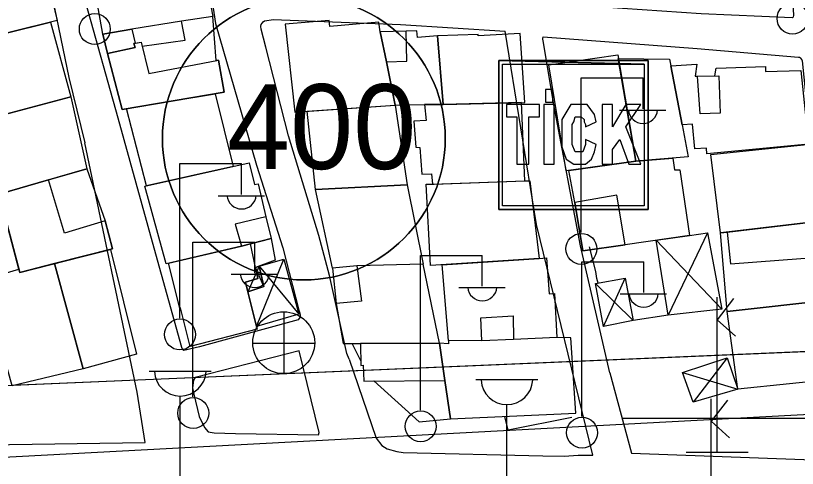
# Model space of a CAD drawing. Extents: x 417997 to 421451, y 4451742 to 4455216.
# Drawn here: x 419193.6 to 419281.9, y 4453640.7 to 4453691.9 of the extents above; entities that cross this region are included whole.
import ezdxf

# ---------------------------------------------------------------- set-up
doc = ezdxf.new("R2010")
doc.units = 0
for name, color, linetype in [('ADAKENARI', 7, 'Continuous'), ('B_Kapi', 7, 'Continuous'), ('B_Mesken', 7, 'Continuous'), ('B_Sundurma', 7, 'Continuous'), ('B_Teras', 7, 'Continuous'), ('KALDIRIM', 7, 'Continuous'), ('LJ_SEMBOL', 7, 'Continuous'), ('PL_TİCK', 7, 'Continuous'), ('S_Cad_Sok_Lambasi', 7, 'Continuous'), ('S_Elektrik_Diregi', 7, 'Continuous'), ('S_Kara_Demy_Trafik_Sinyal', 7, 'Continuous'), ('S_Rogar_Kapagi', 7, 'Continuous'), ('Sinir_Duvar_tek_tarafa_ait', 7, 'Continuous'), ('SM_TAKS', 7, 'Continuous'), ('TR_TİCK', 7, 'Continuous'), ('Yol_Kaldirim_kenari_bordurtasi', 7, 'Continuous'), ('Yol_Sose', 7, 'Continuous')]:
    doc.layers.add(name, color=color, linetype=linetype)

msp = doc.modelspace()

# ---------------------------------------------------------------- linework, layer by layer
at = {"layer": 'ADAKENARI'}
msp.add_line((419123.723, 4453647.173), (419322.839, 4453655.614), dxfattribs=at)
msp.add_line((419123.723, 4453647.173), (419322.839, 4453655.614), dxfattribs=at)
at = {"layer": 'B_Kapi'}
msp.add_lwpolyline([(419259.283, 4453662.174), (419259.171, 4453662.944)], dxfattribs=at)
at = {"layer": 'B_Mesken'}
for points in [[(419203.449, 4453689.791), (419201.814, 4453698.973), (419214.149, 4453700.811), (419215.877, 4453691.806), (419212.331, 4453691.272), (419206.703, 4453690.371)], [(419187.627, 4453688.689), (419185.456, 4453697.539), (419196.149, 4453700.118), (419198.258, 4453691.342)], [(419212.331, 4453691.272), (419206.703, 4453690.371), (419203.449, 4453689.791), (419203.982, 4453687.601), (419205.615, 4453681.291), (419217.156, 4453683.223), (419216.504, 4453686.857), (419216.256, 4453686.81), (419215.877, 4453691.806)], [(419190.17, 4453680.146), (419189.544, 4453679.907), (419187.09, 4453688.417), (419187.627, 4453688.689), (419197.53, 4453691.16), (419199.81, 4453682.704)], [(419224.066, 4453690.944), (419225.127, 4453680.993), (419236.484, 4453681.753), (419235.489, 4453686.652), (419234.799, 4453690.048), (419234.618, 4453691.136), (419229.097, 4453690.661), (419229.021, 4453691.34)], [(419237.712, 4453690.119), (419234.799, 4453690.048), (419235.489, 4453686.652), (419236.484, 4453681.753), (419239.798, 4453681.84), (419241.918, 4453681.825), (419241.274, 4453689.597), (419239.02, 4453689.423), (419238.945, 4453690.156)], [(419241.274, 4453689.597), (419241.918, 4453681.825), (419251.132, 4453682.082), (419250.624, 4453689.853), (419245.867, 4453689.59), (419245.868, 4453689.753)], [(419255.809, 4453674.356), (419253.851, 4453686.344), (419261.638, 4453687.454), (419263.699, 4453675.44)], [(419261.711, 4453687.03), (419267.505, 4453686.983), (419267.644, 4453686.211), (419268.943, 4453679.527), (419269.618, 4453675.937), (419263.699, 4453675.44)], [(419282.327, 4453685.695), (419283.19, 4453677.347), (419271.716, 4453676.268), (419271.673, 4453676.907), (419270.371, 4453676.817), (419270.091, 4453679.637), (419268.943, 4453679.527), (419267.644, 4453686.211), (419270.588, 4453686.414), (419270.407, 4453685.047), (419270.673, 4453685.059), (419272.634, 4453685.076), (419272.784, 4453685.961), (419278.345, 4453686.146), (419278.351, 4453685.57)], [(419191.689, 4453671.712), (419190.521, 4453676.686), (419191.022, 4453676.817), (419190.17, 4453680.146), (419199.81, 4453682.704), (419201.622, 4453674.559)], [(419216.122, 4453683.05), (419218.152, 4453674.841), (419208.381, 4453672.644), (419206.107, 4453681.373)], [(419241.918, 4453681.825), (419239.798, 4453681.84), (419240.001, 4453680.019), (419238.587, 4453679.975), (419238.808, 4453677.013), (419239.27, 4453676.983), (419239.49, 4453673.967), (419240.577, 4453673.986), (419240.686, 4453672.817), (419251.157, 4453673.215), (419250.746, 4453682.071)], [(419227.48, 4453672.227), (419226.525, 4453681.087), (419236.484, 4453681.753), (419237.825, 4453672.751)], [(419273.242, 4453667.327), (419272.169, 4453676.202), (419283.729, 4453677.403), (419284.8, 4453668.679)], [(419267.885, 4453675.791), (419268.064, 4453674.461), (419268.661, 4453674.456), (419269.742, 4453667.042), (419262.491, 4453665.979), (419257.68, 4453665.31), (419256.802, 4453670.769), (419256.098, 4453674.396), (419263.699, 4453675.44)], [(419221.876, 4453669.13), (419222.45, 4453666.69), (419219.106, 4453665.831), (419210.586, 4453663.822), (419208.186, 4453672.601), (419219.988, 4453675.253), (419220.577, 4453672.789), (419220.982, 4453672.877)], [(419201.622, 4453674.559), (419203.706, 4453668.694), (419204.521, 4453665.515), (419197.961, 4453663.846), (419194.058, 4453662.853), (419193.959, 4453663.223), (419191.689, 4453671.712), (419197.308, 4453673.323)], [(419240.472, 4453663.623), (419239.997, 4453672.815), (419240.874, 4453672.817), (419251.157, 4453673.215), (419251.724, 4453673.223), (419252.747, 4453664.433)], [(419239.658, 4453663.804), (419232.154, 4453663.59), (419229.381, 4453663.329), (419227.48, 4453672.227), (419237.825, 4453672.751)], [(419179.471, 4453668.455), (419181.528, 4453659.652), (419190.199, 4453662.11), (419193.959, 4453663.223), (419191.689, 4453671.712), (419190.994, 4453671.434)], [(419274.012, 4453658.445), (419273.242, 4453667.327), (419274.029, 4453667.419), (419284.8, 4453668.679), (419285.31, 4453664.673), (419285.841, 4453659.739)], [(419219.832, 4453660.663), (419220.874, 4453656.423), (419213.316, 4453654.479), (419212.215, 4453658.831), (419212.158, 4453658.817), (419210.862, 4453663.888), (419219.106, 4453665.831), (419220.112, 4453666.089), (419222.45, 4453666.69), (419222.923, 4453664.248), (419220.681, 4453663.406), (419220.948, 4453662.148), (419219.562, 4453661.753), (419219.832, 4453660.663)], [(419204.284, 4453665.454), (419207.256, 4453653.626), (419201.228, 4453651.97), (419197.961, 4453663.846)], [(419252.747, 4453664.433), (419253.589, 4453664.502), (419253.902, 4453660.451), (419254.512, 4453660.478), (419254.756, 4453655.505), (419249.855, 4453655.256), (419246.267, 4453655.132), (419242.529, 4453655.143), (419241.798, 4453663.71)], [(419190.199, 4453662.11), (419193.959, 4453663.223), (419194.058, 4453662.853), (419197.961, 4453663.846), (419201.228, 4453651.97), (419193.177, 4453650.029), (419192.288, 4453653.298), (419192.515, 4453653.359)], [(419229.381, 4453663.329), (419229.809, 4453659.342), (419230.615, 4453654.799), (419232.572, 4453654.811), (419241.489, 4453654.851), (419239.658, 4453663.804), (419232.154, 4453663.59)], [(419274.012, 4453658.445), (419285.841, 4453659.739), (419286.911, 4453650.855), (419275.218, 4453649.668)], [(419242.529, 4453655.143), (419242.498, 4453654.763), (419241.489, 4453654.851), (419242.08, 4453650.635), (419242.756, 4453646.284), (419256.923, 4453646.936), (419256.34, 4453655.471), (419254.756, 4453655.505), (419249.855, 4453655.256), (419246.267, 4453655.132)], [(419242.756, 4453646.284), (419242.08, 4453650.635), (419241.489, 4453654.851), (419232.572, 4453654.811), (419232.607, 4453652.311), (419232.879, 4453652.363), (419232.946, 4453650.569), (419234.089, 4453650.578), (419239.189, 4453645.947)]]:
    msp.add_lwpolyline(points, close=True, dxfattribs=at)
at = {"layer": 'B_Sundurma'}
for p, q in [((419271.79, 4453667.327), (419267.33, 4453658.036)), ((419273.412, 4453658.699), (419265.989, 4453666.492)), ((419220.798, 4453656.731), (419223.893, 4453664.354)), ((419221.106, 4453663.566), (419219.832, 4453660.663)), ((419221.641, 4453661.271), (419220.681, 4453663.406)), ((419221.106, 4453663.566), (419225.59, 4453658.121)), ((419259.143, 4453661.583), (419263.386, 4453657.432)), ((419260.045, 4453656.756), (419262.47, 4453662.187)), ((419274.008, 4453653.214), (419270.16, 4453648.181)), ((419268.976, 4453651.536), (419275.218, 4453649.668))]:
    msp.add_line(p, q, dxfattribs=at)
for points in [[(419269.742, 4453667.042), (419271.79, 4453667.327), (419273.412, 4453658.699), (419267.33, 4453658.036), (419265.989, 4453666.492)], [(419220.798, 4453656.731), (419219.832, 4453660.663), (419221.641, 4453661.271), (419221.106, 4453663.566), (419223.893, 4453664.354), (419225.59, 4453658.121)], [(419221.106, 4453663.566), (419221.641, 4453661.271), (419219.832, 4453660.663), (419219.562, 4453661.753), (419219.562, 4453661.753), (419220.948, 4453662.148), (419220.681, 4453663.406)], [(419260.045, 4453656.756), (419259.143, 4453661.583), (419262.47, 4453662.187), (419263.386, 4453657.432)], [(419268.976, 4453651.536), (419274.008, 4453653.214), (419275.218, 4453649.668), (419270.16, 4453648.181)]]:
    msp.add_lwpolyline(points, close=True, dxfattribs=at)
at = {"layer": 'B_Teras'}
for points in [[(419207.891, 4453688.437), (419212.726, 4453689.133), (419212.331, 4453691.272), (419206.703, 4453690.371), (419207.106, 4453688.764), (419207.776, 4453688.905)], [(419206.703, 4453690.371), (419207.106, 4453688.764), (419206.958, 4453688.733), (419207.097, 4453688.28), (419203.982, 4453687.601), (419203.449, 4453689.791)], [(419234.799, 4453690.048), (419235.489, 4453686.652), (419237.804, 4453686.748), (419237.712, 4453690.119)], [(419205.615, 4453681.291), (419203.982, 4453687.601), (419207.097, 4453688.28), (419206.958, 4453688.733), (419207.776, 4453688.905), (419208.645, 4453685.365), (419216.504, 4453686.857), (419217.156, 4453683.223)], [(419270.952, 4453680.789), (419270.673, 4453685.059), (419273.059, 4453685.08), (419273.22, 4453680.879)], [(419210.586, 4453663.822), (419208.186, 4453672.601), (419219.988, 4453675.253), (419220.577, 4453672.789), (419220.982, 4453672.877), (419221.876, 4453669.13), (419218.394, 4453668.309), (419219.106, 4453665.831)], [(419191.689, 4453671.712), (419194.058, 4453662.853), (419204.521, 4453665.515), (419203.706, 4453668.694), (419199.084, 4453667.291), (419197.308, 4453673.323)], [(419256.802, 4453670.769), (419257.68, 4453665.31), (419262.491, 4453665.979), (419261.532, 4453671.574)], [(419274.029, 4453667.419), (419274.381, 4453663.833), (419285.31, 4453664.673), (419284.8, 4453668.679)], [(419220.681, 4453663.406), (419220.112, 4453666.089), (419222.45, 4453666.69), (419222.923, 4453664.248)], [(419241.489, 4453654.851), (419239.658, 4453663.804), (419232.154, 4453663.59), (419232.666, 4453659.592), (419229.809, 4453659.342), (419230.615, 4453654.799), (419232.572, 4453654.811)], [(419246.267, 4453655.132), (419246.162, 4453657.716), (419249.823, 4453657.957), (419249.855, 4453655.256)], [(419232.572, 4453654.811), (419232.607, 4453652.311), (419232.879, 4453652.363), (419232.946, 4453650.569), (419242.08, 4453650.635), (419241.489, 4453654.851)]]:
    msp.add_lwpolyline(points, close=True, dxfattribs=at)
at = {"layer": 'KALDIRIM'}
msp.add_line((419186.217, 4453641.661), (419323.38, 4453648.975), dxfattribs=at)
msp.add_line((419186.217, 4453641.661), (419323.38, 4453648.975), dxfattribs=at)
at = {"layer": 'LJ_SEMBOL'}
for points in [[(419248.194, 4453686.831), (419264.648, 4453686.409), (419264.648, 4453670.377), (419248.616, 4453670.377), (419248.616, 4453686.409), (419264.648, 4453686.409), (419248.194, 4453686.831), (419248.194, 4453669.955), (419265.07, 4453669.955), (419265.07, 4453686.831), (419248.194, 4453686.831)], [(419248.194, 4453686.831), (419264.648, 4453686.409), (419264.648, 4453670.377), (419248.616, 4453670.377), (419248.616, 4453686.409), (419264.648, 4453686.409), (419248.194, 4453686.831), (419248.194, 4453669.955), (419265.07, 4453669.955), (419265.07, 4453686.831), (419248.194, 4453686.831)], [(419253.461, 4453683.523), (419253.461, 4453682.116), (419254.305, 4453682.116), (419254.305, 4453683.523), (419253.461, 4453683.523)], [(419253.461, 4453683.523), (419253.461, 4453682.116), (419254.305, 4453682.116), (419254.305, 4453683.523), (419253.461, 4453683.523)], [(419249.073, 4453681.835), (419249.073, 4453680.429), (419250.254, 4453680.429), (419250.254, 4453675.085), (419251.604, 4453675.085), (419251.604, 4453680.429), (419252.786, 4453680.429), (419252.786, 4453681.835), (419249.073, 4453681.835)], [(419249.073, 4453681.835), (419249.073, 4453680.429), (419250.254, 4453680.429), (419250.254, 4453675.085), (419251.604, 4453675.085), (419251.604, 4453680.429), (419252.786, 4453680.429), (419252.786, 4453681.835), (419249.073, 4453681.835)], [(419253.292, 4453681.835), (419253.292, 4453675.085), (419254.473, 4453675.085), (419254.473, 4453681.835), (419253.292, 4453681.835)], [(419253.292, 4453681.835), (419253.292, 4453675.085), (419254.473, 4453675.085), (419254.473, 4453681.835), (419253.292, 4453681.835)], [(419258.017, 4453677.897), (419258.017, 4453677.335), (419257.68, 4453676.491), (419257.342, 4453676.491), (419256.836, 4453676.491), (419256.498, 4453677.335), (419256.498, 4453678.741), (419256.498, 4453679.585), (419256.667, 4453679.866), (419256.836, 4453680.429), (419257.342, 4453680.429), (419257.511, 4453680.429), (419257.848, 4453680.147), (419257.848, 4453679.866), (419258.017, 4453679.585), (419258.017, 4453679.304), (419259.198, 4453679.866), (419259.03, 4453680.71), (419258.186, 4453681.835), (419257.511, 4453681.835), (419256.33, 4453681.835), (419255.317, 4453680.147), (419255.317, 4453678.741), (419255.317, 4453677.053), (419255.823, 4453675.647), (419256.667, 4453675.085), (419257.511, 4453675.085), (419258.017, 4453675.085), (419258.692, 4453675.647), (419259.03, 4453676.491), (419259.198, 4453677.335), (419258.017, 4453677.897)], [(419258.017, 4453677.897), (419258.017, 4453677.335), (419257.68, 4453676.491), (419257.342, 4453676.491), (419256.836, 4453676.491), (419256.498, 4453677.335), (419256.498, 4453678.741), (419256.498, 4453679.585), (419256.667, 4453679.866), (419256.836, 4453680.429), (419257.342, 4453680.429), (419257.511, 4453680.429), (419257.848, 4453680.147), (419257.848, 4453679.866), (419258.017, 4453679.585), (419258.017, 4453679.304), (419259.198, 4453679.866), (419259.03, 4453680.71), (419258.186, 4453681.835), (419257.511, 4453681.835), (419256.33, 4453681.835), (419255.317, 4453680.147), (419255.317, 4453678.741), (419255.317, 4453677.053), (419255.823, 4453675.647), (419256.667, 4453675.085), (419257.511, 4453675.085), (419258.017, 4453675.085), (419258.692, 4453675.647), (419259.03, 4453676.491), (419259.198, 4453677.335), (419258.017, 4453677.897)], [(419259.874, 4453681.835), (419259.874, 4453675.085), (419261.055, 4453675.085), (419261.055, 4453676.772), (419261.899, 4453677.897), (419262.911, 4453675.085), (419264.261, 4453675.085), (419262.574, 4453679.304), (419264.261, 4453681.835), (419262.574, 4453681.835), (419261.055, 4453679.304), (419261.055, 4453681.835), (419259.874, 4453681.835)], [(419259.874, 4453681.835), (419259.874, 4453675.085), (419261.055, 4453675.085), (419261.055, 4453676.772), (419261.899, 4453677.897), (419262.911, 4453675.085), (419264.261, 4453675.085), (419262.574, 4453679.304), (419264.261, 4453681.835), (419262.574, 4453681.835), (419261.055, 4453679.304), (419261.055, 4453681.835), (419259.874, 4453681.835)]]:
    msp.add_lwpolyline(points, dxfattribs=at)
at = {"layer": 'PL_TİCK'}
msp.add_lwpolyline([(419164.709, 4453648.91), (419322.839, 4453655.614), (419331.388, 4453665.934), (419326.377, 4453700.333), (419324.954, 4453710.095), (419151.813, 4453700.114), (419164.709, 4453648.91)], dxfattribs=at)
msp.add_lwpolyline([(419164.709, 4453648.91), (419322.839, 4453655.614), (419331.388, 4453665.934), (419326.377, 4453700.333), (419324.954, 4453710.095), (419151.813, 4453700.114), (419164.709, 4453648.91)], dxfattribs=at)
at = {"layer": 'S_Cad_Sok_Lambasi'}
for p, q in [((419208.685, 4453651.703), (419215.685, 4453651.703)), ((419245.612, 4453650.73), (419252.612, 4453650.73)), ((419212.185, 4453634.203), (419212.185, 4453648.879)), ((419249.112, 4453633.23), (419249.112, 4453647.905))]:
    msp.add_line(p, q, dxfattribs=at)
for centre in [(419212.185, 4453651.808), (419249.112, 4453650.834)]:
    msp.add_arc(centre, 2.929, 183.298, 356.90719, dxfattribs=at)
at = {"layer": 'S_Elektrik_Diregi'}
for p, q in [((419257.5, 4453667.352), (419257.5, 4453684.852)), ((419257.5, 4453684.852), (419264.5, 4453684.852)), ((419264.5, 4453681.352), (419264.5, 4453684.852)), ((419261.84, 4453681.212), (419267.09, 4453681.212)), ((419212.123, 4453657.673), (419212.123, 4453675.173)), ((419212.123, 4453675.173), (419219.123, 4453675.173)), ((419219.123, 4453671.673), (419219.123, 4453675.173)), ((419216.463, 4453671.533), (419221.713, 4453671.533)), ((419213.621, 4453648.787), (419213.621, 4453666.287)), ((419213.621, 4453666.287), (419220.621, 4453666.287)), ((419220.621, 4453662.787), (419220.621, 4453666.287)), ((419239.33, 4453647.283), (419239.33, 4453664.783)), ((419239.33, 4453664.783), (419246.33, 4453664.783)), ((419246.33, 4453661.283), (419246.33, 4453664.783)), ((419257.575, 4453646.568), (419257.575, 4453664.069)), ((419257.575, 4453664.069), (419264.575, 4453664.069)), ((419264.575, 4453660.568), (419264.575, 4453664.069)), ((419217.961, 4453662.647), (419223.211, 4453662.647)), ((419243.67, 4453661.143), (419248.92, 4453661.143)), ((419261.915, 4453660.428), (419267.165, 4453660.428))]:
    msp.add_line(p, q, dxfattribs=at)
for centre in [(419281.402, 4453691.563), (419202.531, 4453690.372), (419257.536, 4453665.517), (419212.159, 4453655.837), (419213.657, 4453646.951), (419239.366, 4453645.448), (419257.611, 4453644.733)]:
    msp.add_circle(centre, 1.75, dxfattribs=at)
for centre in [(419264.501, 4453681.365), (419219.124, 4453671.686), (419220.622, 4453662.799), (419246.331, 4453661.296), (419264.576, 4453660.581)]:
    msp.add_arc(centre, 1.658, 184.83843, 355.14641, dxfattribs=at)
at = {"layer": 'S_Kara_Demy_Trafik_Sinyal'}
for p, q in [((419272.874, 4453642.539), (419272.874, 4453660.039)), ((419274.729, 4453659.887), (419272.874, 4453657.507)), ((419272.874, 4453657.507), (419274.946, 4453655.636)), ((419272.208, 4453631.065), (419272.208, 4453648.566)), ((419274.063, 4453648.413), (419272.208, 4453646.033)), ((419272.208, 4453646.033), (419274.28, 4453644.162)), ((419269.374, 4453642.539), (419276.374, 4453642.539))]:
    msp.add_line(p, q, dxfattribs=at)
at = {"layer": 'S_Rogar_Kapagi'}
for p, q in [((419223.937, 4453651.377), (419223.937, 4453658.377)), ((419220.367, 4453654.842), (419227.367, 4453654.842))]:
    msp.add_line(p, q, dxfattribs=at)
msp.add_circle((419223.884, 4453654.906), 3.5, dxfattribs=at)
at = {"layer": 'Sinir_Duvar_tek_tarafa_ait'}
for points in [[(419259.171, 4453662.944), (419258.463, 4453665.746)], [(419259.449, 4453661.638), (419259.283, 4453662.174)], [(419267.33, 4453658.036), (419263.386, 4453657.432)], [(419232.599, 4453652.84), (419231.62, 4453654.805)], [(419256.455, 4453646.441), (419249.245, 4453645.025), (419248.894, 4453646.566)]]:
    msp.add_lwpolyline(points, dxfattribs=at)
at = {"layer": 'SM_TAKS'}
msp.add_circle((419226.16, 4453677.997), 15.988, dxfattribs=at)
msp.add_circle((419226.16, 4453677.997), 15.988, dxfattribs=at)
at = {"layer": 'TR_TİCK'}
for points in [[(419151.813, 4453700.114), (419164.709, 4453648.91), (419322.839, 4453655.614), (419331.388, 4453665.934), (419326.377, 4453700.333), (419324.954, 4453710.095), (419151.813, 4453700.114)], [(419151.813, 4453700.114), (419164.709, 4453648.91), (419322.839, 4453655.614), (419331.388, 4453665.934), (419326.377, 4453700.333), (419324.954, 4453710.095), (419151.813, 4453700.114)], [(419248.194, 4453686.831), (419265.07, 4453686.831), (419265.07, 4453669.955), (419248.194, 4453669.955), (419248.194, 4453686.831)], [(419248.194, 4453686.831), (419265.07, 4453686.831), (419265.07, 4453669.955), (419248.194, 4453669.955), (419248.194, 4453686.831)]]:
    msp.add_lwpolyline(points, dxfattribs=at)
for start, end in [(0, 180), (0, 180), (180, 0), (180, 0)]:
    msp.add_arc((419226.16, 4453677.997), 15.988, start, end, dxfattribs=at)
at = {"layer": 'Yol_Kaldirim_kenari_bordurtasi'}
msp.add_lwpolyline([(419262.139, 4453646.388), (419286.592, 4453646.357)], dxfattribs=at)
at = {"layer": 'Yol_Sose'}
for points in [[(419181.616, 4453717.224), (419191.669, 4453719.982), (419191.897, 4453720.006), (419192.048, 4453719.999), (419192.266, 4453719.895), (419192.312, 4453719.823), (419192.459, 4453719.586), (419194.007, 4453709.754), (419194.958, 4453705.16), (419197.737, 4453693.872), (419199.608, 4453684.904), (419201.397, 4453677.515)], [(419168.56, 4453712.386), (419185.34, 4453646.986), (419185.967, 4453644.161), (419186.128, 4453643.943), (419186.993, 4453643.72), (419190.296, 4453643.37), (419208.236, 4453643.617)], [(419213.234, 4453711.514), (419213.597, 4453710.708), (419213.869, 4453710.052), (419214, 4453709.462), (419214.696, 4453700.735), (419216.165, 4453691.019), (419220.79, 4453674.978), (419223.79, 4453665.625), (419225.591, 4453658.582), (419225.704, 4453658.242), (419225.754, 4453657.999), (419225.745, 4453657.871), (419225.722, 4453657.748), (419225.536, 4453657.495), (419214.363, 4453654.44)], [(419214.363, 4453654.44), (419212.575, 4453654.027), (419212.489, 4453654.098), (419212.36, 4453654.347), (419209.255, 4453665.582), (419205.169, 4453680.293), (419201.501, 4453693.343), (419199.266, 4453704.512)], [(419281.146, 4453699.181), (419281.506, 4453691.893), (419281.491, 4453691.747), (419281.444, 4453691.673), (419281.429, 4453691.665), (419281.378, 4453691.655), (419271.059, 4453692.113), (419257.727, 4453692.987), (419246.214, 4453694.013), (419233.38, 4453694.836), (419230.163, 4453694.941), (419225.895, 4453695.134)], [(419227.872, 4453667.036), (419224.438, 4453678.285), (419221.862, 4453688.327), (419221.33, 4453690.365), (419221.298, 4453690.662), (419221.296, 4453690.708), (419221.333, 4453690.889), (419221.577, 4453691.179), (419221.719, 4453691.297), (419221.757, 4453691.313), (419222.68, 4453691.455), (419237.095, 4453690.878), (419248.923, 4453690.151)], [(419231.278, 4453653.028), (419234.331, 4453644.102), (419234.979, 4453643.28), (419235.576, 4453642.893), (419236.664, 4453642.612), (419237.372, 4453642.498), (419253.184, 4453642.103), (419255.583, 4453642.085), (419257.166, 4453642.181), (419258.817, 4453642.204), (419252.469, 4453668.276), (419248.923, 4453690.151)], [(419260.768, 4453651.494), (419257.448, 4453665.859), (419254.454, 4453681.605), (419253.203, 4453689.042), (419253.175, 4453689.218), (419253.18, 4453689.332), (419253.218, 4453689.476), (419270.629, 4453688.193), (419282.066, 4453687.213), (419282.178, 4453687.177), (419282.252, 4453687.121), (419282.442, 4453686.91), (419282.506, 4453686.79), (419283.953, 4453672.394), (419285.944, 4453659.325), (419286.17, 4453657.577)], [(419208.236, 4453643.617), (419207.307, 4453649.318), (419201.397, 4453677.515)], [(419231.278, 4453653.028), (419231.028, 4453653.668), (419229.049, 4453662.488), (419227.872, 4453667.036)], [(419260.768, 4453651.494), (419263.204, 4453642.421), (419286.774, 4453641.53), (419286.17, 4453657.577)]]:
    msp.add_lwpolyline(points, dxfattribs=at)
msp.add_lwpolyline([(419213.892, 4453650.984), (419213.699, 4453650.686), (419213.555, 4453649.787), (419213.74, 4453649.077), (419214.32, 4453646.565), (419214.937, 4453645.333), (419215.342, 4453644.812), (419216.023, 4453644.725), (419218.449, 4453644.625), (419227.829, 4453644.497), (419227.886, 4453644.769), (419225.615, 4453653.972)], close=True, dxfattribs=at)

# ---------------------------------------------------------------- texts
at = {"layer": 'SM_TAKS'}
msp.add_text('400', height=9.5928, dxfattribs=at).set_placement((419217.471, 4453674.546))
msp.add_text('400', height=9.5928, dxfattribs=at).set_placement((419217.471, 4453674.546))

doc.saveas('drawing.dxf')
